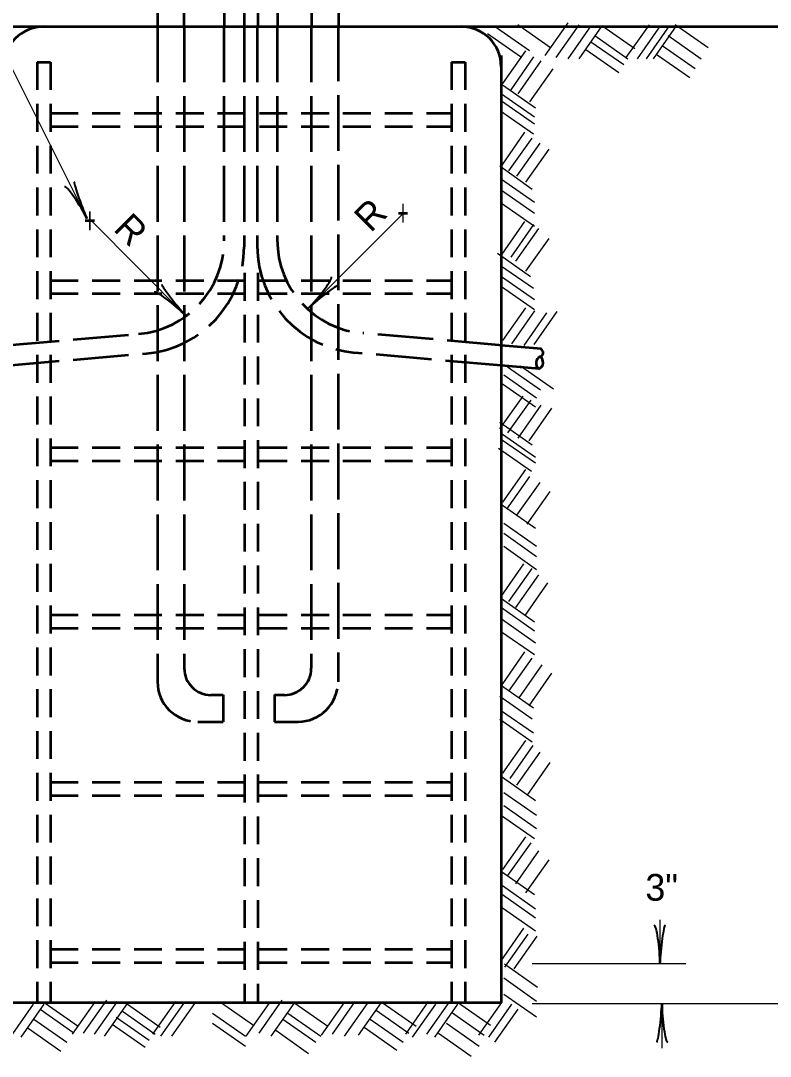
# Model space of a CAD drawing. Extents: x -1 to 679, y 0 to 440.
# Drawn here: x 332.7 to 389.2, y 50.7 to 128.7 of the extents above; entities that cross this region are included whole.
import ezdxf

# ---------------------------------------------------------------- set-up
doc = ezdxf.new("R2010")
doc.units = 0
doc.header["$LTSCALE"] = 0.7
doc.linetypes.add('LONG_DASHED', pattern=[7.5, 6, -1.5])
doc.linetypes.add('MEDIUM_DASHED', pattern=[4.5, 3, -1.5])
doc.layers.add('1', color=7, linetype='Continuous', lineweight=53)

msp = doc.modelspace()

# ---------------------------------------------------------------- linework, layer by layer
at = {"layer": '1', "lineweight": 25}
for p, q in [((337.7117, 113.7762), (326.0517, 137.0762)), ((368.5718, 128.1562), (371.0517, 126.4363)), ((370.1717, 128.3963), (372.6517, 126.6562)), ((372.2317, 126.0562), (373.9717, 128.5162)), ((373.0718, 125.8962), (374.7917, 128.3762)), ((373.9717, 125.8162), (375.7117, 128.2962)), ((374.8117, 125.8162), (376.5317, 128.2962)), ((376.5118, 128.3162), (378.9917, 126.5763)), ((378.3517, 125.8962), (380.0917, 128.3762)), ((379.1918, 125.8162), (380.9317, 128.2962)), ((379.8717, 125.8162), (381.6117, 128.2962)), ((380.3918, 125.8162), (382.1318, 128.2962)), ((382.0317, 128.3963), (384.5118, 126.6562)), ((367.8918, 127.7163), (370.3717, 125.9762)), ((375.9917, 127.5562), (378.4717, 125.8162)), ((381.5118, 127.5562), (383.9917, 125.8162)), ((369.0517, 123.9363), (370.7917, 126.4162)), ((375.3117, 126.4962), (377.7917, 124.7762)), ((375.6918, 127.0962), (378.1717, 125.3762)), ((381.0517, 126.7963), (383.5317, 125.0763)), ((369.6717, 123.4762), (371.3918, 125.9562)), ((370.1918, 123.1762), (371.9317, 125.6562)), ((380.6717, 126.1162), (383.1517, 124.3962)), ((371.0917, 122.5763), (372.8317, 125.0562)), ((369.0317, 123.8563), (371.5118, 122.1162)), ((368.9518, 123.1762), (371.4317, 121.4363)), ((368.9518, 122.6362), (371.4317, 120.9162)), ((368.8717, 121.8962), (371.3517, 120.1562)), ((368.9917, 117.7963), (370.7117, 120.2762)), ((369.5118, 117.3563), (371.2518, 119.8362)), ((370.1117, 116.9762), (371.8517, 119.4562)), ((370.7917, 116.5162), (372.5317, 118.9962)), ((368.8117, 117.7362), (371.2717, 115.9962)), ((368.9518, 116.7362), (371.4317, 115.0162)), ((368.9518, 115.9162), (371.4317, 114.1762)), ((368.9518, 114.9363), (371.4317, 113.1962)), ((368.9917, 111.0763), (370.7117, 113.5562)), ((369.6717, 110.8563), (371.3918, 113.3162)), ((370.0317, 110.5562), (371.7717, 113.0162)), ((370.7917, 109.7963), (372.5317, 112.2762)), ((368.6517, 111.1562), (371.1318, 109.4162)), ((368.8717, 110.2362), (371.3517, 108.5162)), ((368.9518, 109.4162), (371.4317, 107.6762)), ((368.9518, 108.6562), (371.4317, 106.9162)), ((369.0517, 104.5763), (370.7917, 107.0562)), ((369.7317, 104.3362), (371.4717, 106.8162)), ((370.6517, 104.1962), (372.3717, 106.6762)), ((371.4117, 104.2762), (373.1318, 106.7562)), ((369.4117, 102.5962), (371.8918, 100.8762)), ((370.3918, 102.6762), (372.8717, 100.9363)), ((369.1117, 101.9963), (371.5917, 100.2562)), ((369.0317, 101.3162), (371.5118, 99.5763)), ((368.8317, 97.9162), (370.5718, 100.3962)), ((369.4317, 97.6162), (371.1717, 100.0962)), ((370.1918, 97.2362), (371.9317, 99.7163)), ((371.0317, 97.0162), (372.7518, 99.4963)), ((368.8117, 98.4363), (371.2717, 96.7163)), ((369.0317, 97.5362), (371.5118, 95.7963)), ((369.0317, 97.0763), (371.5118, 95.3563)), ((368.7317, 96.4762), (371.2117, 94.7362)), ((369.0517, 92.3962), (370.7917, 94.8762)), ((369.3517, 91.8762), (371.0917, 94.3362)), ((370.1117, 91.4162), (371.8517, 93.8962)), ((370.8717, 90.7362), (372.6117, 93.2163)), ((369.0317, 92.1762), (371.5118, 90.4363)), ((369.1117, 90.8162), (371.5917, 89.0763)), ((369.1117, 90.0562), (371.5917, 88.3162)), ((369.1117, 89.0763), (371.5917, 87.3362)), ((368.9117, 85.2963), (370.6318, 87.7562)), ((369.5118, 84.9162), (371.2518, 87.3962)), ((370.0317, 84.4562), (371.7717, 86.9363)), ((370.7317, 83.8563), (372.4518, 86.3362)), ((368.9518, 85.1363), (371.4317, 83.3962)), ((368.9518, 84.4562), (371.4317, 82.7163)), ((369.0317, 83.5562), (371.5118, 81.8162)), ((368.9518, 82.6363), (371.4317, 80.9162)), ((368.9917, 78.6363), (370.7117, 81.1162)), ((369.5118, 78.1762), (371.2518, 80.6562)), ((370.2717, 77.6562), (372.0118, 80.1363)), ((371.0317, 77.0562), (372.7518, 79.5162)), ((368.8717, 78.6363), (371.3517, 76.8962)), ((368.8117, 77.7963), (371.2717, 76.0763)), ((368.8717, 76.7362), (371.3517, 75.0162)), ((368.8117, 76.0562), (371.2717, 74.3362)), ((369.0517, 71.9762), (370.7917, 74.4562)), ((369.5917, 71.5962), (371.3317, 74.0763)), ((370.1117, 71.0763), (371.8517, 73.5562)), ((370.8717, 70.3162), (372.6117, 72.7963)), ((369.0317, 71.6762), (371.5118, 69.9363)), ((369.1117, 70.5362), (371.5917, 68.8162)), ((369.1117, 69.5562), (371.5917, 67.8162)), ((368.9518, 68.7963), (371.4317, 67.0763)), ((369.0517, 64.7163), (370.7917, 67.1962)), ((369.4317, 64.2763), (371.1717, 66.7362)), ((370.0317, 63.6562), (371.7717, 66.1363)), ((370.7917, 62.9763), (372.5317, 65.4562)), ((368.9518, 64.5763), (371.4317, 62.8362)), ((369.0317, 63.5162), (371.5118, 61.7762)), ((369.0317, 62.8362), (371.5118, 61.0962)), ((369.0317, 61.8362), (371.5118, 60.1163)), ((380.8918, 60.9363), (380.8918, 57.6362)), ((368.9117, 57.8362), (370.6318, 60.3162)), ((369.2117, 57.3762), (370.9518, 59.8562)), ((369.8918, 57.2362), (371.6318, 59.7162)), ((369.1717, 57.6163), (371.6517, 55.8762)), ((371.2518, 57.6362), (382.8517, 57.6362)), ((369.1117, 56.5562), (371.5917, 54.8162)), ((334.5517, 54.6562), (337.0317, 52.9363)), ((336.6117, 52.3162), (338.3517, 54.7963)), ((337.4518, 52.3962), (339.1918, 54.8762)), ((338.2717, 52.3162), (340.0118, 54.7963)), ((339.0317, 52.1762), (340.7717, 54.6362)), ((342.6717, 52.3162), (344.3918, 54.7963)), ((343.2717, 52.1762), (345.0118, 54.6362)), ((344.1117, 52.1762), (345.8317, 54.6362)), ((347.7717, 54.7362), (350.2518, 52.9962)), ((349.6918, 52.1762), (351.4317, 54.6362)), ((350.6918, 52.3962), (352.4117, 54.8762)), ((351.5917, 52.1762), (353.3317, 54.6362)), ((353.3717, 54.6562), (355.8517, 52.9363)), ((355.3717, 52.2362), (357.1117, 54.7162)), ((356.2117, 52.3162), (357.9317, 54.7963)), ((357.1117, 52.1762), (358.8517, 54.6362)), ((358.1717, 52.2362), (359.9117, 54.7162)), ((360.0317, 54.6562), (362.5118, 52.9363)), ((361.7317, 52.3162), (363.4518, 54.7963)), ((363.3117, 52.3162), (365.0517, 54.7963)), ((365.6318, 54.7362), (368.1117, 52.9962)), ((367.2518, 52.2362), (368.9717, 54.7162)), ((369.1117, 55.3362), (371.5917, 53.6163)), ((371.2518, 54.6362), (393.4317, 54.6362)), ((381.0317, 54.6362), (381.0317, 51.2563)), ((331.9317, 52.0962), (333.6717, 54.5763)), ((332.7518, 52.0962), (334.4917, 54.5763)), ((334.1717, 54.2162), (336.6517, 52.4763)), ((340.3717, 54.0562), (342.8517, 52.3162)), ((340.7518, 54.5763), (343.2317, 52.8562)), ((347.1717, 53.8962), (349.6517, 52.1762)), ((352.8517, 53.8962), (355.3317, 52.1762)), ((359.5118, 54.1362), (361.9717, 52.3962)), ((362.2518, 52.0962), (363.9917, 54.5763)), ((363.9117, 52.0962), (365.6517, 54.5763)), ((365.1717, 53.9763), (367.6517, 52.2563)), ((367.9917, 52.0962), (369.7317, 54.5763)), ((368.4518, 51.7162), (370.1918, 54.1962)), ((333.7117, 53.4562), (336.1918, 51.7162)), ((339.6117, 53.0763), (342.0917, 51.3362)), ((339.9117, 53.5962), (342.3918, 51.8762)), ((347.1717, 53.1562), (349.6517, 51.4162)), ((352.4717, 53.4562), (354.9518, 51.7162)), ((359.0517, 53.4562), (361.5317, 51.7162)), ((364.7917, 53.1562), (367.2717, 51.4162)), ((333.2717, 52.7762), (335.7317, 51.0362)), ((351.9317, 52.6163), (354.4117, 50.8762)), ((358.5917, 52.8562), (361.0718, 51.1163)), ((364.1918, 52.3962), (366.6717, 50.6562))]:
    msp.add_line(p, q, dxfattribs=at)
at = {"layer": '1'}
for p, q in [((348.0517, 135.2763), (348.0517, 128.2163)), ((349.5517, 135.2763), (349.5517, 128.2163)), ((350.5718, 135.2763), (350.5718, 128.2163)), ((352.0718, 135.2763), (352.0718, 128.2163)), ((343.0118, 134.3363), (343.0118, 128.2362)), ((345.0118, 134.3363), (345.0118, 128.2362)), ((354.6318, 134.3363), (354.6318, 128.2763)), ((356.6517, 134.3363), (356.6517, 128.2763)), ((302.8317, 128.2362), (337.2117, 128.2362)), ((334.4518, 128.2362), (391.8918, 128.2362)), ((383.2717, 128.2362), (399.5917, 128.2362)), ((368.9317, 126.0562), (368.9317, 54.6962)), ((371.9317, 103.9562), (368.9117, 104.2163)), ((371.7917, 102.4562), (368.9117, 102.6962))]:
    msp.add_line(p, q, dxfattribs=at)
at = {"layer": '1', "linetype": 'LONG_DASHED'}
for p, q in [((343.0118, 128.2362), (343.0118, 78.8762)), ((345.0317, 128.2362), (345.0317, 79.8962)), ((348.0317, 128.2362), (348.0317, 112.0962)), ((349.5517, 128.2362), (349.5517, 111.6362)), ((350.5317, 128.2362), (350.5317, 111.6962)), ((352.0517, 128.2362), (352.0517, 112.1562)), ((354.6117, 128.2362), (354.6117, 79.8962)), ((356.6318, 128.3162), (356.6318, 78.8762)), ((331.4317, 104.1962), (341.5917, 105.0763)), ((369.0317, 104.2163), (358.4917, 105.1362)), ((331.4317, 102.6762), (342.1918, 103.6162)), ((368.9117, 102.6962), (357.8918, 103.6562)), ((347.0517, 77.8762), (347.9717, 77.8762)), ((347.9717, 77.8762), (347.9717, 75.8563)), ((351.8517, 77.8762), (352.5917, 77.8762)), ((351.8517, 77.8762), (351.8517, 75.8563)), ((346.0517, 75.8563), (347.9717, 75.8563)), ((351.8517, 75.8563), (353.6117, 75.8563))]:
    msp.add_line(p, q, dxfattribs=at)
at = {"layer": '1', "linetype": 'MEDIUM_DASHED'}
for p, q in [((333.9518, 125.5562), (333.9518, 54.6962)), ((333.9518, 125.5562), (334.9518, 125.5562)), ((334.9518, 125.5562), (334.9518, 54.6962)), ((365.1918, 125.5562), (365.1918, 54.6962)), ((365.1918, 125.5562), (366.2117, 125.5562)), ((366.2117, 125.5562), (366.2117, 54.6962)), ((334.9518, 121.7163), (365.1918, 121.7163)), ((334.9518, 120.7163), (365.1918, 120.7163)), ((349.5718, 109.6762), (349.5718, 54.6962)), ((350.5718, 109.6762), (350.5718, 54.6962)), ((334.9518, 109.1162), (365.1918, 109.1162)), ((334.9518, 108.1162), (365.1918, 108.1162)), ((334.9518, 96.5162), (365.1918, 96.5162)), ((334.9518, 95.5162), (365.1918, 95.5162)), ((334.9518, 83.9162), (365.1918, 83.9162)), ((334.9518, 82.9162), (365.1918, 82.9162)), ((334.9518, 71.3162), (365.1918, 71.3162)), ((334.9518, 70.3162), (365.1918, 70.3162)), ((334.9518, 58.7162), (365.1918, 58.7162)), ((334.9518, 57.7162), (365.1918, 57.7162))]:
    msp.add_line(p, q, dxfattribs=at)
at = {"layer": '1', "lineweight": 35}
for p, q in [((354.3918, 107.0162), (361.5118, 114.1362)), ((345.1318, 106.4762), (338.0118, 113.6162))]:
    msp.add_line(p, q, dxfattribs=at)
at = {"layer": '1'}
msp.add_lwpolyline([(331.4317, 125.2163), (331.4317, 54.6962), (368.9317, 54.6962)], dxfattribs=at)
for centre, radius, start, end in [((334.4522, 125.2117), 3.024, 90, 180), ((365.9001, 125.2117), 3.024, 0, 90), ((371.5502, 102.9321), 0.5346, 295.57592, 55.60116)]:
    msp.add_arc(centre, radius, start, end, dxfattribs=at)
at = {"layer": '1', "lineweight": 25}
msp.add_arc((334.4522, 125.2117), 3.024, 90, 180, dxfattribs=at)
at = {"layer": '1', "linetype": 'LONG_DASHED'}
for centre, radius, start, end in [((340.984, 112.106), 7.056, 275.00041, 0), ((341.488, 111.6441), 8.064, 275.00013, 0), ((358.5988, 111.697), 8.064, 180, 264.9999), ((359.1028, 112.1589), 7.056, 180, 264.9999), ((347.0522, 79.8877), 2.016, 180, 270), ((352.5962, 79.8877), 2.016, 270, 0), ((346.0442, 78.8797), 3.024, 180, 270), ((353.6042, 78.8797), 3.024, 270, 0)]:
    msp.add_arc(centre, radius, start, end, dxfattribs=at)
at = {"layer": '1', "lineweight": 40}
for centre, major_axis, ratio, start_param, end_param in [((337.3902, 114.879), (0.6334, -1.6628), 0.07063, 3.1407148, 5.41811), ((336.9635, 114.6326), (0.9458, -1.5396), 0.122415, 0.8963533, 3.1415927), ((354.9634, 107.9855), (-1.1615, -1.3841), 0.122415, 0.8963533, 3.1415927), ((344.4849, 107.4309), (-1.1267, 1.3771), 0.07063, 6.2823074, 8.5597026), ((355.332, 107.6586), (-1.3771, -1.1267), 0.07063, 3.1407148, 5.41811), ((344.158, 107.0622), (1.3841, -1.1615), 0.122415, 0.8963533, 3.1415927), ((380.6088, 58.7349), (0.1574, -1.8), 0.122415, 0.8963533, 3.1415927), ((381.1006, 58.7644), (0.1771, 1.7705), 0.07063, 6.2823074, 8.5597026), ((380.8253, 53.4999), (0.1771, 1.7705), 0.07063, 3.1407148, 5.41811), ((381.3171, 53.5294), (-0.1574, 1.8), 0.122415, 0.8963533, 3.1415927)]:
    msp.add_ellipse(centre, major_axis=major_axis, ratio=ratio, start_param=start_param, end_param=end_param, dxfattribs=at)
at = {"layer": '1'}
for centre, major_axis, ratio, start_param, end_param in [((371.7458, 103.6914), (-0.2991, 0.1888), 0.884789, 2.395874, 4.712389), ((372.0821, 102.8913), (-0.4869, -0.2208), 0.984898, 4.7124662, 6.8138568)]:
    msp.add_ellipse(centre, major_axis=major_axis, ratio=ratio, start_param=start_param, end_param=end_param, dxfattribs=at)

# ---------------------------------------------------------------- texts
for rotation, p in [(45, (359.0917, 112.6562)), (315, (339.6318, 112.9162))]:
    msp.add_text('R', height=2.016, rotation=rotation, dxfattribs=at).set_placement(p)
at = {"layer": '1', "width": 0.55}
for p in [(361.0917, 113.1962), (337.4917, 112.6362)]:
    msp.add_text('+', height=2.016, dxfattribs=at).set_placement(p)
at = {"layer": '1'}
msp.add_text('3"', height=2.016, dxfattribs=at).set_placement((379.7917, 62.3762))

doc.saveas('drawing.dxf')
